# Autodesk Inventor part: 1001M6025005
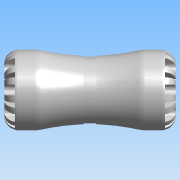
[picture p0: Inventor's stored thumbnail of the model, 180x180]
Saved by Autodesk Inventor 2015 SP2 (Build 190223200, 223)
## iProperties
Created: 2016-12
Part Number: 1001M6025005
Material: PVC-Piping
Description: PLASSON COUPLER METRIC TO IMPERIAL 25X1/2" SERIES 1
Document SubType Name: Modeling
Designer: KIM
Mass: 95.2094 g
Surface Area: 200.83 cm^2
Volume: 68.0067 cm^3
Density: 1.4 g/cm^3
Appearance: Smooth - White
ILogicFactory: False
Author: KIM
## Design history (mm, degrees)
derived "1001M.ipt"
feature "Solid1::1001M.ipt"
tag "TaggingFeature1"
body "Solid1"
other parameters: "d2" = 48, "d11" = 6.3, "d13" = 6.3, "d14" = 0, "d16" = 360 deg, "d18" = 8 deg, "d19" = 0.5, "d20" = 8 deg, "d21" = 0.5, "d23" = 0, "d25" = 360 deg, "d27" = 18.8, "d28" = 7.5, "d29" = 7.5, "d30" = 12.348, "d31" = 0, "d33" = 0, "d38" = 0.47, "d44" = 25, "d46" = 39.95, "d47" = 47, "d50" = 360 deg, "d54" = 0.513, "d61" = 31.25, "d66" = 1.05833, "d70" = 6.3, "d72" = 6.3, "d73" = 0, "d75" = 360 deg, "d77" = 8 deg, "d78" = 8 deg, "d79" = 0.5, "d80" = 0.5, "d82" = 0, "d84" = 360 deg, "d87" = 31.25, "d93" = 12.7, "d_" = 25, "E_" = 47, "l_" = 48, "d_1" = 12.7, "d12" = 31.25, "d42" = 47, "d52" = 7.875, "d68" = 47, "d69" = 31.25, "d71" = 7.875
